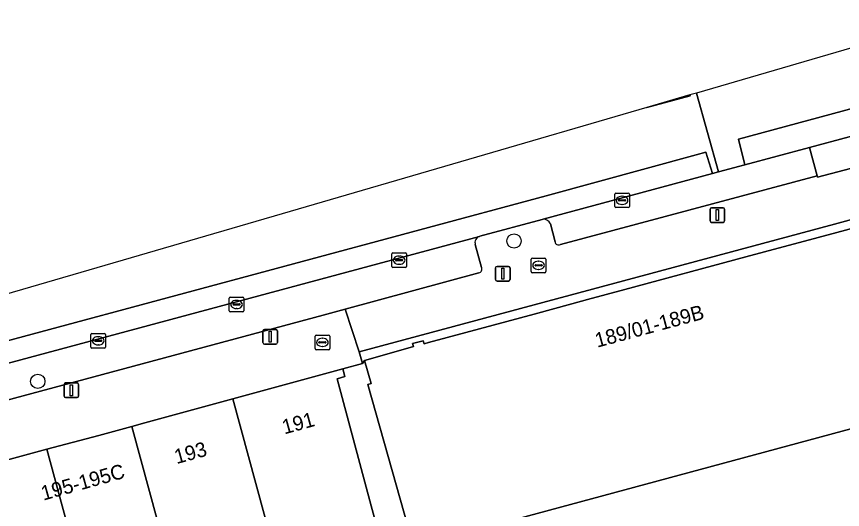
# Model space of a CAD drawing. Extents: x 159716 to 160783, y 383290 to 384031.
# Drawn here: x 159807.9 to 159864.4, y 383616.7 to 383650.4 of the extents above; entities that cross this region are included whole.
import ezdxf

# ---------------------------------------------------------------- set-up
doc = ezdxf.new("R2010")
doc.units = 0
for name, color, linetype in [('IMGEO_Boom', 7, 'Continuous'), ('IMGEO_Brandkraan', 7, 'Continuous'), ('IMGEO_Erf', 7, 'Continuous'), ('IMGEO_Groenvoorziening', 7, 'Continuous'), ('IMGEO_Kolk', 7, 'Continuous'), ('IMGEO_Lichtmast', 7, 'Continuous'), ('IMGEO_Pand', 7, 'Continuous'), ('IMGEO_Pand_nummerreeks', 7, 'Continuous'), ('IMGEO_Parkeervlak_open', 7, 'Continuous'), ('IMGEO_Rijbaan_lokaal_gesloten', 7, 'Continuous'), ('IMGEO_Rijbaan_lokaal_open', 7, 'Continuous'), ('IMGEO_Rioolput', 7, 'Continuous'), ('IMGEO_Voetpad_open', 7, 'Continuous')]:
    doc.layers.add(name, color=color, linetype=linetype)

msp = doc.modelspace()

# ---------------------------------------------------------------- linework, layer by layer
at = {"layer": 'IMGEO_Boom'}
for centre in [(159841.911, 383635.04), (159809.324, 383625.432)]:
    msp.add_circle(centre, 0.489, dxfattribs=at)
at = {"layer": 'IMGEO_Brandkraan'}
for p, q in [((159828.3, 383627.675), (159828.3, 383628.527)), ((159828.375, 383628.601), (159829.227, 383628.601)), ((159828.602, 383628.144), (159829, 383628.144)), ((159828.788, 383628.381), (159828.813, 383628.381)), ((159829.301, 383628.527), (159829.301, 383627.675)), ((159829.227, 383627.601), (159828.375, 383627.601)), ((159828.559, 383628.095), (159828.559, 383628.107)), ((159828.997, 383628.058), (159828.599, 383628.058)), ((159828.811, 383627.821), (159828.786, 383627.821)), ((159829.043, 383628.107), (159829.043, 383628.095))]:
    msp.add_line(p, q, dxfattribs=at)
for points in [[(159828.3, 383627.675), (159828.3, 383628.527)], [(159828.375, 383628.601), (159829.227, 383628.601)], [(159829.301, 383628.527), (159829.301, 383627.675)], [(159829.227, 383627.601), (159828.375, 383627.601)]]:
    msp.add_lwpolyline(points, dxfattribs=at)
for centre, radius, start, end in [((159828.377, 383628.525), 0.0765, 91.552, 178.448), ((159828.377, 383628.525), 0.0765, 91.552, 178.448), ((159828.599, 383628.104), 0.0403, 85.8775, 175.7526), ((159829.004, 383628.106), 0.0386, 1.7309, 96.639), ((159829.225, 383628.525), 0.0765, 1.552, 88.448), ((159829.225, 383628.525), 0.0765, 1.552, 88.448), ((159828.377, 383627.677), 0.0765, 181.552, 268.448), ((159828.377, 383627.677), 0.0765, 181.552, 268.448), ((159828.596, 383628.094), 0.0366, 178.938, 274.7102), ((159829, 383628.101), 0.043, 264.8664, 352.4533), ((159829.225, 383627.677), 0.0765, 271.552, 358.448), ((159829.225, 383627.677), 0.0765, 271.552, 358.448)]:
    msp.add_arc(centre, radius, start, end, dxfattribs=at)
for centre, major_axis, ratio, start_param, end_param in [((159828.787, 383628.101), (-0.387, 0.002), 0.722429, 4.712389, 7.853982), ((159828.812, 383628.101), (-0.39, 0.002), 0.717154, 1.570796, 4.712389)]:
    msp.add_ellipse(centre, major_axis=major_axis, ratio=ratio, start_param=start_param, end_param=end_param, dxfattribs=at)
at = {"layer": 'IMGEO_Erf'}
msp.add_lwpolyline([(159845.381, 383571.333), (159843.064, 383591.222), (159837.629, 383611.992), (159835.792, 383611.496), (159831.912, 383625.22), (159832.125, 383625.276), (159831.677, 383626.864), (159831.539, 383626.662), (159830.19, 383626.287), (159830.335, 383625.757), (159829.805, 383625.611), (159832.133, 383616.92), (159834.9, 383606.758), (159839.341, 383590.45), (159841.885, 383590.73), (159846.252, 383555.697)], dxfattribs=at)
at = {"layer": 'IMGEO_Groenvoorziening'}
msp.add_lwpolyline([(159867.563, 383642.898), (159862.136, 383641.425), (159862.639, 383639.499), (159862.663, 383639.405), (159868.154, 383640.85)], close=True, dxfattribs=at)
at = {"layer": 'IMGEO_Kolk'}
for p, q in [((159848.874, 383638.321), (159849.726, 383638.321)), ((159848.799, 383637.395), (159848.799, 383638.247)), ((159849.058, 383637.815), (159849.058, 383637.827)), ((159849.496, 383637.778), (159849.098, 383637.778)), ((159849.101, 383637.864), (159849.499, 383637.864)), ((159849.287, 383638.101), (159849.312, 383638.101)), ((159849.542, 383637.827), (159849.542, 383637.815)), ((159849.8, 383638.247), (159849.8, 383637.395)), ((159849.726, 383637.321), (159848.874, 383637.321)), ((159849.31, 383637.541), (159849.285, 383637.541)), ((159833.549, 383633.301), (159833.549, 383634.153)), ((159833.624, 383634.227), (159834.476, 383634.227)), ((159833.851, 383633.77), (159834.249, 383633.77)), ((159834.037, 383634.007), (159834.062, 383634.007)), ((159834.55, 383634.153), (159834.55, 383633.301)), ((159834.476, 383633.227), (159833.624, 383633.227)), ((159833.808, 383633.721), (159833.808, 383633.733)), ((159834.246, 383633.684), (159833.848, 383633.684)), ((159834.06, 383633.447), (159834.035, 383633.447)), ((159834.292, 383633.733), (159834.292, 383633.721)), ((159822.423, 383630.269), (159822.423, 383631.121)), ((159822.498, 383631.195), (159823.35, 383631.195)), ((159822.911, 383630.975), (159822.936, 383630.975)), ((159823.424, 383631.121), (159823.424, 383630.269)), ((159822.682, 383630.689), (159822.682, 383630.701)), ((159823.12, 383630.652), (159822.722, 383630.652)), ((159822.725, 383630.738), (159823.123, 383630.738)), ((159822.934, 383630.415), (159822.909, 383630.415)), ((159823.166, 383630.701), (159823.166, 383630.689)), ((159823.35, 383630.195), (159822.498, 383630.195)), ((159813.035, 383628.709), (159813.887, 383628.709)), ((159812.96, 383627.783), (159812.96, 383628.635)), ((159813.219, 383628.203), (159813.219, 383628.215)), ((159813.657, 383628.166), (159813.259, 383628.166)), ((159813.262, 383628.252), (159813.66, 383628.252)), ((159813.448, 383628.489), (159813.473, 383628.489)), ((159813.703, 383628.215), (159813.703, 383628.203)), ((159813.961, 383628.635), (159813.961, 383627.783)), ((159813.887, 383627.709), (159813.035, 383627.709)), ((159813.471, 383627.929), (159813.446, 383627.929))]:
    msp.add_line(p, q, dxfattribs=at)
for points in [[(159848.874, 383638.321), (159849.726, 383638.321)], [(159848.799, 383637.395), (159848.799, 383638.247)], [(159849.8, 383638.247), (159849.8, 383637.395)], [(159849.726, 383637.321), (159848.874, 383637.321)], [(159833.549, 383633.301), (159833.549, 383634.153)], [(159833.624, 383634.227), (159834.476, 383634.227)], [(159834.55, 383634.153), (159834.55, 383633.301)], [(159834.476, 383633.227), (159833.624, 383633.227)], [(159822.423, 383630.269), (159822.423, 383631.121)], [(159822.498, 383631.195), (159823.35, 383631.195)], [(159823.424, 383631.121), (159823.424, 383630.269)], [(159823.35, 383630.195), (159822.498, 383630.195)], [(159813.035, 383628.709), (159813.887, 383628.709)], [(159812.96, 383627.783), (159812.96, 383628.635)], [(159813.961, 383628.635), (159813.961, 383627.783)], [(159813.887, 383627.709), (159813.035, 383627.709)]]:
    msp.add_lwpolyline(points, dxfattribs=at)
for centre, radius, start, end in [((159848.876, 383638.245), 0.0765, 91.552, 178.448), ((159848.876, 383638.245), 0.0765, 91.552, 178.448), ((159849.724, 383638.245), 0.0765, 1.552, 88.448), ((159849.724, 383638.245), 0.0765, 1.552, 88.448), ((159849.098, 383637.824), 0.0403, 85.8775, 175.7526), ((159849.095, 383637.814), 0.0366, 178.938, 274.7102), ((159849.499, 383637.821), 0.043, 264.8664, 352.4533), ((159849.503, 383637.826), 0.0386, 1.7309, 96.639), ((159848.876, 383637.397), 0.0765, 181.552, 268.448), ((159848.876, 383637.397), 0.0765, 181.552, 268.448), ((159849.724, 383637.397), 0.0765, 271.552, 358.448), ((159849.724, 383637.397), 0.0765, 271.552, 358.448), ((159833.626, 383634.151), 0.0765, 91.552, 178.448), ((159833.626, 383634.151), 0.0765, 91.552, 178.448), ((159833.848, 383633.73), 0.0403, 85.8775, 175.7526), ((159834.253, 383633.732), 0.0386, 1.7309, 96.639), ((159834.474, 383634.151), 0.0765, 1.552, 88.448), ((159834.474, 383634.151), 0.0765, 1.552, 88.448), ((159833.626, 383633.303), 0.0765, 181.552, 268.448), ((159833.626, 383633.303), 0.0765, 181.552, 268.448), ((159833.845, 383633.72), 0.0366, 178.938, 274.7102), ((159834.249, 383633.727), 0.043, 264.8664, 352.4533), ((159834.474, 383633.303), 0.0765, 271.552, 358.448), ((159834.474, 383633.303), 0.0765, 271.552, 358.448), ((159822.5, 383631.119), 0.0765, 91.552, 178.448), ((159822.5, 383631.119), 0.0765, 91.552, 178.448), ((159823.348, 383631.119), 0.0765, 1.552, 88.448), ((159823.348, 383631.119), 0.0765, 1.552, 88.448), ((159822.722, 383630.698), 0.0403, 85.8775, 175.7526), ((159822.719, 383630.688), 0.0366, 178.938, 274.7102), ((159823.123, 383630.695), 0.043, 264.8664, 352.4533), ((159823.127, 383630.7), 0.0386, 1.7309, 96.639), ((159822.5, 383630.271), 0.0765, 181.552, 268.448), ((159822.5, 383630.271), 0.0765, 181.552, 268.448), ((159823.348, 383630.271), 0.0765, 271.552, 358.448), ((159823.348, 383630.271), 0.0765, 271.552, 358.448), ((159813.037, 383628.633), 0.0765, 91.552, 178.448), ((159813.037, 383628.633), 0.0765, 91.552, 178.448), ((159813.885, 383628.633), 0.0765, 1.552, 88.448), ((159813.885, 383628.633), 0.0765, 1.552, 88.448), ((159813.259, 383628.212), 0.0403, 85.8775, 175.7526), ((159813.256, 383628.202), 0.0366, 178.938, 274.7102), ((159813.66, 383628.209), 0.043, 264.8664, 352.4533), ((159813.664, 383628.214), 0.0386, 1.7309, 96.639), ((159813.037, 383627.785), 0.0765, 181.552, 268.448), ((159813.037, 383627.785), 0.0765, 181.552, 268.448), ((159813.885, 383627.785), 0.0765, 271.552, 358.448), ((159813.885, 383627.785), 0.0765, 271.552, 358.448)]:
    msp.add_arc(centre, radius, start, end, dxfattribs=at)
for centre, major_axis, ratio, start_param, end_param in [((159849.286, 383637.821), (-0.387, 0.002), 0.722429, 4.712389, 7.853982), ((159849.311, 383637.821), (-0.39, 0.002), 0.717154, 1.570796, 4.712389), ((159834.036, 383633.727), (-0.387, 0.002), 0.722429, 4.712389, 7.853982), ((159834.061, 383633.727), (-0.39, 0.002), 0.717154, 1.570796, 4.712389), ((159822.91, 383630.695), (-0.387, 0.002), 0.722429, 4.712389, 7.853982), ((159822.935, 383630.695), (-0.39, 0.002), 0.717154, 1.570796, 4.712389), ((159813.447, 383628.209), (-0.387, 0.002), 0.722429, 4.712389, 7.853982), ((159813.472, 383628.209), (-0.39, 0.002), 0.717154, 1.570796, 4.712389)]:
    msp.add_ellipse(centre, major_axis=major_axis, ratio=ratio, start_param=start_param, end_param=end_param, dxfattribs=at)
at = {"layer": 'IMGEO_Lichtmast'}
for p, q in [((159855.326, 383636.415), (159855.326, 383637.215)), ((159855.326, 383637.215), (159855.326, 383636.415)), ((159855.426, 383637.315), (159856.216, 383637.315)), ((159856.216, 383637.315), (159855.426, 383637.315)), ((159856.316, 383637.215), (159856.316, 383636.415)), ((159856.316, 383636.415), (159856.316, 383637.215)), ((159856.216, 383636.315), (159855.426, 383636.315)), ((159855.426, 383636.315), (159856.216, 383636.315)), ((159840.646, 383632.398), (159840.646, 383633.198)), ((159840.646, 383633.198), (159840.646, 383632.398)), ((159840.746, 383633.298), (159841.536, 383633.298)), ((159841.536, 383633.298), (159840.746, 383633.298)), ((159841.636, 383633.198), (159841.636, 383632.398)), ((159841.636, 383632.398), (159841.636, 383633.198)), ((159841.536, 383632.298), (159840.746, 383632.298)), ((159840.746, 383632.298), (159841.536, 383632.298)), ((159824.729, 383628.082), (159824.729, 383628.882)), ((159824.729, 383628.882), (159824.729, 383628.082)), ((159824.829, 383628.982), (159825.619, 383628.982)), ((159825.619, 383628.982), (159824.829, 383628.982)), ((159825.719, 383628.882), (159825.719, 383628.082)), ((159825.719, 383628.082), (159825.719, 383628.882)), ((159825.619, 383627.982), (159824.829, 383627.982)), ((159824.829, 383627.982), (159825.619, 383627.982)), ((159811.231, 383625.326), (159812.021, 383625.326)), ((159812.021, 383625.326), (159811.231, 383625.326)), ((159811.131, 383624.426), (159811.131, 383625.226)), ((159811.131, 383625.226), (159811.131, 383624.426)), ((159812.121, 383625.226), (159812.121, 383624.426)), ((159812.121, 383624.426), (159812.121, 383625.226)), ((159812.021, 383624.326), (159811.231, 383624.326)), ((159811.231, 383624.326), (159812.021, 383624.326))]:
    msp.add_line(p, q, dxfattribs=at)
for points in [[(159855.746, 383637.19), (159855.896, 383637.19), (159855.896, 383636.44), (159855.746, 383636.44), (159855.746, 383637.19)], [(159841.066, 383633.173), (159841.216, 383633.173), (159841.216, 383632.423), (159841.066, 383632.423), (159841.066, 383633.173)], [(159825.149, 383628.857), (159825.299, 383628.857), (159825.299, 383628.107), (159825.149, 383628.107), (159825.149, 383628.857)], [(159811.551, 383625.201), (159811.701, 383625.201), (159811.701, 383624.451), (159811.551, 383624.451), (159811.551, 383625.201)]]:
    msp.add_lwpolyline(points, dxfattribs=at)
for centre, start, end in [((159855.426, 383637.215), 90, 180), ((159855.426, 383637.215), 90, 180), ((159856.216, 383637.215), 0, 90), ((159856.216, 383637.215), 360, 90), ((159855.426, 383636.415), 180, 270), ((159855.426, 383636.415), 180, 270), ((159856.216, 383636.415), 270, 0), ((159856.216, 383636.415), 270, 0), ((159840.746, 383633.198), 90, 180), ((159840.746, 383633.198), 90, 180), ((159841.536, 383633.198), 0, 90), ((159841.536, 383633.198), 360, 90), ((159840.746, 383632.398), 180, 270), ((159840.746, 383632.398), 180, 270), ((159841.536, 383632.398), 270, 0), ((159841.536, 383632.398), 270, 0), ((159824.829, 383628.882), 90, 180), ((159824.829, 383628.882), 90, 180), ((159825.619, 383628.882), 0, 90), ((159825.619, 383628.882), 360, 90), ((159824.829, 383628.082), 180, 270), ((159824.829, 383628.082), 180, 270), ((159825.619, 383628.082), 270, 0), ((159825.619, 383628.082), 270, 0), ((159811.231, 383625.226), 90, 180), ((159811.231, 383625.226), 90, 180), ((159812.021, 383625.226), 0, 90), ((159812.021, 383625.226), 360, 90), ((159811.231, 383624.426), 180, 270), ((159811.231, 383624.426), 180, 270), ((159812.021, 383624.426), 270, 0), ((159812.021, 383624.426), 270, 0)]:
    msp.add_arc(centre, 0.1, start, end, dxfattribs=at)
at = {"layer": 'IMGEO_Pand'}
msp.add_lwpolyline([(159871.604, 383637.681), (159863.994, 383635.627), (159861.438, 383634.938), (159860.326, 383634.638), (159857.768, 383633.947), (159849.488, 383631.714), (159846.938, 383631.025), (159845.854, 383630.733), (159843.294, 383630.042), (159838.611, 383628.779), (159836.055, 383628.089), (159835.755, 383628.009), (159835.694, 383628.212), (159834.97, 383628.022), (159835.026, 383627.809), (159834.97, 383627.793), (159831.677, 383626.864), (159832.125, 383625.276), (159831.912, 383625.22), (159835.792, 383611.496), (159837.629, 383611.992), (159839.07, 383612.381), (159838.335, 383614.999), (159873.243, 383624.427)], dxfattribs=at)
for points in [[(159832.133, 383616.92), (159829.805, 383625.611), (159830.335, 383625.757), (159830.19, 383626.287), (159822.67, 383624.23), (159826.462, 383610.291), (159825.994, 383610.097), (159828.949, 383599.764), (159829.124, 383599.118), (159830.053, 383595.709), (159831.367, 383590.881), (159838.901, 383590.474), (159839.341, 383590.45), (159834.9, 383606.758)], [(159822.67, 383624.23), (159816.654, 383622.584), (159815.752, 383622.342), (159818.104, 383613.692), (159818.775, 383611.226), (159819.835, 383607.322), (159820.763, 383603.912), (159821.059, 383602.823), (159824.02, 383603.628), (159822.519, 383609.152), (159825.994, 383610.097), (159826.462, 383610.291)], [(159815.752, 383622.342), (159813.492, 383621.736), (159809.943, 383620.783), (159812.715, 383610.6), (159813.07, 383610.697), (159813.424, 383609.398), (159814.393, 383605.84), (159815.321, 383602.432), (159820.763, 383603.912), (159819.835, 383607.322), (159818.775, 383611.226), (159818.104, 383613.692)], [(159813.424, 383609.398), (159813.07, 383610.697), (159812.715, 383610.6), (159809.943, 383620.783), (159804.906, 383619.431), (159799.199, 383617.899), (159798.873, 383617.812), (159805.09, 383594.973), (159808.971, 383594.434), (159814.732, 383593.633), (159817.877, 383593.196), (159817.46, 383594.653), (159815.321, 383602.432), (159814.393, 383605.84)]]:
    msp.add_lwpolyline(points, close=True, dxfattribs=at)
at = {"layer": 'IMGEO_Parkeervlak_open'}
for points in [[(159862.639, 383639.499), (159862.136, 383641.425), (159857.701, 383640.246), (159855.908, 383639.763), (159855.496, 383639.651), (159843.895, 383636.522)], [(159845.083, 383634.794), (159862.639, 383639.499)], [(159844.395, 383636.202), (159844.715, 383634.991)], [(159839.547, 383635.354), (159783.978, 383620.4), (159781.674, 383619.726)], [(159839.683, 383633.233), (159839.261, 383634.795)], [(159785.659, 383618.347), (159828.847, 383629.956), (159830.349, 383630.364), (159839.508, 383632.85)]]:
    msp.add_lwpolyline(points, dxfattribs=at)
for centre, radius, start, end in [((159843.923, 383636.014), 0.508, 21.6597, 93.1018), ((159839.677, 383634.935), 0.439, 107.2517, 198.5572), ((159844.967, 383635.019), 0.253, 186.2708, 297.4066), ((159839.437, 383633.114), 0.273, 285.096, 25.7909)]:
    msp.add_arc(centre, radius, start, end, dxfattribs=at)
at = {"layer": 'IMGEO_Rijbaan_lokaal_gesloten'}
msp.add_lwpolyline([(159870.849, 383645.682), (159857.264, 383641.995), (159857.701, 383640.246), (159862.136, 383641.425), (159867.563, 383642.898), (159873.378, 383644.509)], dxfattribs=at)
for points in [[(159853.941, 383645.03), (159851.006, 383644.174), (159853.957, 383644.972)], [(159839.547, 383635.354), (159839.578, 383635.362), (159843.84, 383636.516), (159843.895, 383636.522), (159855.496, 383639.651), (159855.035, 383641.117), (159854.37, 383640.927), (159844.116, 383638.137), (159783.577, 383621.851), (159783.978, 383620.4)]]:
    msp.add_lwpolyline(points, close=True, dxfattribs=at)
at = {"layer": 'IMGEO_Rijbaan_lokaal_open'}
msp.add_lwpolyline([(159872.658, 383649.417), (159872.372, 383650.4), (159854.392, 383645.161), (159855.908, 383639.763), (159857.701, 383640.246), (159857.264, 383641.995), (159870.849, 383645.682)], dxfattribs=at)
msp.add_lwpolyline([(159782.892, 383624.33), (159782.892, 383624.329), (159783.577, 383621.851), (159844.116, 383638.137), (159854.37, 383640.927), (159855.035, 383641.117), (159855.496, 383639.651), (159855.908, 383639.763), (159854.392, 383645.161), (159853.941, 383645.03), (159853.957, 383644.972), (159851.006, 383644.174), (159826.588, 383637.06)], close=True, dxfattribs=at)
at = {"layer": 'IMGEO_Rioolput'}
for p, q in [((159843.088, 383632.944), (159843.088, 383633.796)), ((159843.163, 383633.87), (159844.015, 383633.87)), ((159844.089, 383633.796), (159844.089, 383632.944)), ((159843.347, 383633.364), (159843.347, 383633.376)), ((159843.785, 383633.327), (159843.387, 383633.327)), ((159843.39, 383633.413), (159843.788, 383633.413)), ((159843.576, 383633.65), (159843.601, 383633.65)), ((159843.831, 383633.376), (159843.831, 383633.364)), ((159844.015, 383632.87), (159843.163, 383632.87)), ((159843.599, 383633.09), (159843.574, 383633.09))]:
    msp.add_line(p, q, dxfattribs=at)
for points in [[(159843.088, 383632.944), (159843.088, 383633.796)], [(159843.163, 383633.87), (159844.015, 383633.87)], [(159844.089, 383633.796), (159844.089, 383632.944)], [(159844.015, 383632.87), (159843.163, 383632.87)]]:
    msp.add_lwpolyline(points, dxfattribs=at)
for centre, radius, start, end in [((159843.165, 383633.794), 0.0765, 91.552, 178.448), ((159843.165, 383633.794), 0.0765, 91.552, 178.448), ((159844.013, 383633.794), 0.0765, 1.552, 88.448), ((159844.013, 383633.794), 0.0765, 1.552, 88.448), ((159843.387, 383633.373), 0.0403, 85.8775, 175.7526), ((159843.384, 383633.363), 0.0366, 178.938, 274.7102), ((159843.788, 383633.37), 0.043, 264.8664, 352.4533), ((159843.792, 383633.375), 0.0386, 1.7309, 96.639), ((159843.165, 383632.946), 0.0765, 181.552, 268.448), ((159843.165, 383632.946), 0.0765, 181.552, 268.448), ((159844.013, 383632.946), 0.0765, 271.552, 358.448), ((159844.013, 383632.946), 0.0765, 271.552, 358.448)]:
    msp.add_arc(centre, radius, start, end, dxfattribs=at)
for centre, major_axis, ratio, start_param, end_param in [((159843.575, 383633.37), (-0.387, 0.002), 0.722429, 4.712389, 7.853982), ((159843.6, 383633.37), (-0.39, 0.002), 0.717154, 1.570796, 4.712389)]:
    msp.add_ellipse(centre, major_axis=major_axis, ratio=ratio, start_param=start_param, end_param=end_param, dxfattribs=at)
at = {"layer": 'IMGEO_Voetpad_open'}
for points in [[(159873.718, 383643.284), (159873.718, 383643.283), (159873.959, 383642.413), (159868.154, 383640.85), (159862.663, 383639.405), (159862.639, 383639.499), (159845.083, 383634.794)], [(159839.508, 383632.85), (159830.349, 383630.364), (159831.316, 383627.447), (159863.843, 383636.185), (159872.198, 383638.482)], [(159843.895, 383636.522), (159843.84, 383636.516), (159839.578, 383635.362), (159839.547, 383635.354)], [(159844.715, 383634.991), (159844.395, 383636.202)], [(159839.261, 383634.795), (159839.683, 383633.233)], [(159804.906, 383619.431), (159809.943, 383620.783), (159813.492, 383621.736), (159815.752, 383622.342), (159816.654, 383622.584), (159822.67, 383624.23), (159830.19, 383626.287), (159831.539, 383626.662), (159831.316, 383627.447), (159830.349, 383630.364), (159828.847, 383629.956), (159785.659, 383618.347)]]:
    msp.add_lwpolyline(points, dxfattribs=at)
for points in [[(159857.768, 383633.947), (159860.326, 383634.638), (159861.438, 383634.938), (159863.994, 383635.627), (159871.604, 383637.681), (159871.547, 383637.893), (159872.286, 383638.092), (159872.327, 383638.103), (159872.198, 383638.482), (159863.843, 383636.185), (159831.316, 383627.447), (159831.539, 383626.662), (159831.677, 383626.864), (159834.97, 383627.793), (159835.026, 383627.809), (159834.97, 383628.022), (159835.694, 383628.212), (159835.755, 383628.009), (159836.055, 383628.089), (159838.611, 383628.779), (159843.294, 383630.042), (159845.854, 383630.733), (159846.938, 383631.025), (159849.488, 383631.714)], [(159845.381, 383571.333), (159846.081, 383571.598), (159844.263, 383585.68), (159850.47, 383586.023), (159850.036, 383587.59), (159849.727, 383588.706), (159849.514, 383588.656), (159849.255, 383589.592), (159849.46, 383589.649), (159845.864, 383602.911), (159849.144, 383603.825), (159849.848, 383601.197), (159877.484, 383608.667), (159877.066, 383610.416), (159878.961, 383610.943), (159877.821, 383614.924), (159877.376, 383614.802), (159875.128, 383623.071), (159873.715, 383622.691), (159873.243, 383624.427), (159838.335, 383614.999), (159839.07, 383612.381), (159837.629, 383611.992), (159843.064, 383591.222)]]:
    msp.add_lwpolyline(points, close=True, dxfattribs=at)
for centre, radius, start, end in [((159843.923, 383636.014), 0.508, 21.6597, 93.1018), ((159839.677, 383634.935), 0.439, 107.2517, 198.5572), ((159844.967, 383635.019), 0.253, 186.2708, 297.4066), ((159839.437, 383633.114), 0.273, 285.096, 25.7909)]:
    msp.add_arc(centre, radius, start, end, dxfattribs=at)

# ---------------------------------------------------------------- texts
at = {"layer": 'IMGEO_Pand_nummerreeks'}
for s, rotation, p in [('189/01-189B', 15.1204, (159847.6, 383627.734)), ('191', 15.3839, (159826.199, 383621.8)), ('193', 15.424, (159818.826, 383619.768)), ('195-195C', 15.6246, (159809.706, 383617.267))]:
    msp.add_text(s, height=1, rotation=rotation, dxfattribs=at).set_placement(p)

doc.saveas('drawing.dxf')
